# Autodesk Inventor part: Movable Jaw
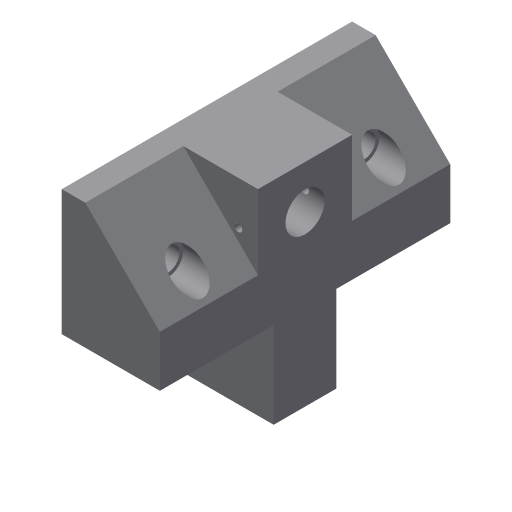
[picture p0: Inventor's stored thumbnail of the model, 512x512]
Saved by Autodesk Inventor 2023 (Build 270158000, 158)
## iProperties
Shininess: 77.0
Length Units: 11269
Angle Units: 11279
Time Units: 11290
Mass Units: 11283
Length Display Precision: 3
Angle Display Precision: 2
Created: 2002-02
Part Number: Movable Jaw
Document SubType Name: Modeling
Designer: ***
Density: 1 g/cm^3
Material: Generic
Appearance: Default
Density: 0.0
Volumn: 0.0
Area: 0.0
PropertySet Name: Model Information
Control State: 0
Master: False
Checked Out: False
Author: ***
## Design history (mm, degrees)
sketch "Sketch2"
  geometry: L1 (2.39, 41.509)-(2.39, 9.509); L2 (2.39, 9.509)-(-22.61, 9.509); L3 (-22.61, 9.509)-(-22.61, 22.509); L4 (-22.61, 22.509)-(-3.61, 41.509); L5 (-3.61, 41.509)-(2.39, 41.509)
  constraints: 10 end point, 2 parallel, 1 perpendicular, 1 vertical
  dimensions: "d0" = 25 distance of L1.end L2.end; "d2" = 13 distance of L2.end L3.end; "d3" = 32 distance between parallel lines of L5 L2; "d4" = 6 distance of L4.end L1.start
extrude "Extrusion1" new body sketch "Sketch2" stored distance "d5" = 74; taper "d6" = 0 deg
sketch "Sketch3"
  geometry: L1 (-19, 25)-(11, 25); L2 (11, 25)-(11, 49); L3 (11, 49)-(-19, 49); L4 (-19, 49)-(-19, 25); L5 (0, 0)-(13, 0) reference; L6 (-19, 74)-(-19, 0) reference; L7 (11.924, 29)-(35, 29); L8 (35, 29)-(35, 45); L9 (35, 45)-(11.924, 45); L10 (11.924, 45)-(11.924, 29); L11 (13, 74)-(13, 0) reference
  constraints: 16 end point, 4 parallel, 2 horizontal, 2 perpendicular, 1 collinear
  dimensions: "d7" = 24 distance of L3.end L1.start; "d8" = 30 distance of L1.start L1.end; "d9" = 25 distance between parallel lines of L5 L1; "d10" = 16 distance of L7.end L8.end; "d11" = 4 distance between parallel lines of L3 L9; "d12" = 22 distance between parallel lines of L11 L8
extrude "Extrusion2" join sketch "Sketch3" distance "d13" = 25; taper "d14" = 0 deg
sketch "Sketch4"
  geometry: L1 (-19, -25)-(-19, -49) reference; L2 (-19, -49)-(0, -49) reference; 1 further point
  dimensions: "d15" = 11 distance from line of L1 point (-8, -37); "d16" = 12 distance from line of L2 point (-8, -37)
hole "Hole1" sketch "Sketch4" at (-8, -37) diameter "d17" = 10; stored, may be unused: countersink angle "d21" = 82 deg, drill point angle "d23" = 0 deg; dims "d18" = 6, "d19" = 4, "d20" = 2, "d22" = 13
sketch "Sketch5"
  geometry: L1 (-19, -49)-(-19, -74) reference; L2 (0, -74)-(13, -74) reference; 1 further point
  dimensions: "d24" = 14 distance from line of L1 point (-5, -62); "d25" = 12 distance from line of L2 point (-5, -62)
hole "Hole2" sketch "Sketch5" at (-5, -62) diameter "d26" = 6; stored, may be unused: countersink angle "d30" = 82 deg, drill point angle "d32" = 0 deg; dims "d27" = 6, "d28" = 8, "d29" = 10, "d31" = 13
mirror "Mirror1"
sketch "Sketch6"
  geometry: L1 (0, 19)-(0, 0) reference; 1 further point
  dimensions: "d33" = 5 distance from line of L1 point (-5, 8); "d34" = 11 vertical distance of L1.start point (-5, 8)
hole "Hole3" sketch "Sketch6" at (-5, 8) diameter "d35" = 2; stored, may be unused: countersink angle "d39" = 82 deg, drill point angle "d41" = 0 deg; dims "d36" = 6, "d37" = 8, "d38" = 10, "d40" = 13
body "Solid1"
